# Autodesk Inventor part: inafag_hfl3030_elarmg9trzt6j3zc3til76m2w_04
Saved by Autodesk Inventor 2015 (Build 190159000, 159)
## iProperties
Company: TraceParts S.A.
Created: 2012-12
Part Number: inafag_hfl3030_elarmg9trzt6j3zc3til76m2w_04
Checked By: TraceParts S.A.
Catalog Web Link: www.traceparts.com
Document SubType Name: Modeling
Designer: TraceParts
Material: Generic
Density: 1 g/cm^3
Appearance: Default
Author: TraceParts
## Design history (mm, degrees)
feature "inafag_hfl3030_elarmg9trzt6j3zc3til76m2w"
body "Solid1"
